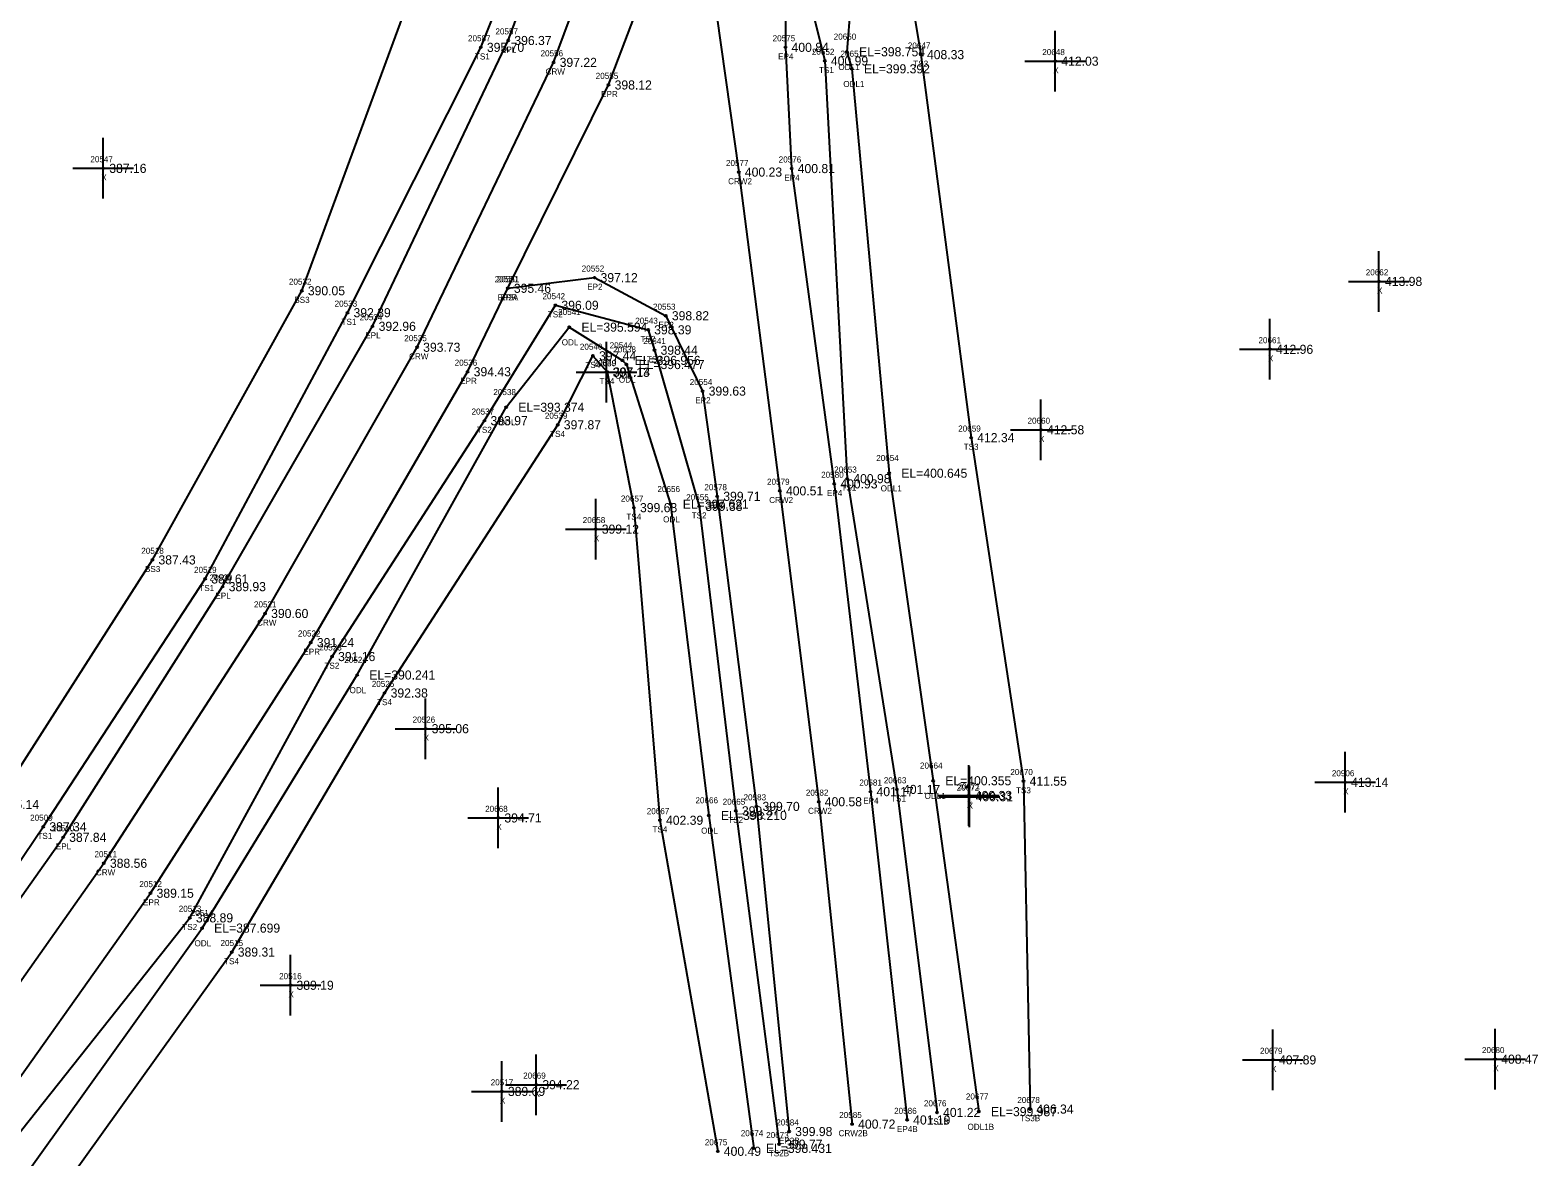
# Model space of a CAD drawing. Extents: x 2116373 to 2118139, y 979529 to 981026.
# Drawn here: x 2117884.9 to 2118133.5, y 980637.9 to 980823.7 of the extents above; entities that cross this region are included whole.
import ezdxf

# ---------------------------------------------------------------- set-up
doc = ezdxf.new("R2010")
doc.units = 0
for name, color, linetype in [('RD_DTM_BkLn1', 7, 'Continuous'), ('RD_DTM_BkLn2', 7, 'Continuous'), ('RD_DTM_BkLn_txCode', 7, 'Continuous'), ('RD_EX_H2O', 7, 'Continuous'), ('RD_EX_H2O_txCode', 7, 'Continuous'), ('RD_EX_Misc', 7, 'Continuous'), ('RD_EX_Misc_txCode', 7, 'Continuous'), ('RD_EX_Road', 7, 'Continuous'), ('RD_EX_Road_txCode', 7, 'Continuous'), ('RD_EX_TX_H2O_ELEV', 7, 'Continuous'), ('RD_EX_TX_Misc_ELEV', 7, 'Continuous'), ('RD_EX_TX_Road_ELEV', 7, 'Continuous'), ('RD_HC_Survey_ELEV', 7, 'Continuous'), ('RD_HC_Survey_txCode', 7, 'Continuous'), ('RD_SMD_Locator', 7, 'Continuous')]:
    doc.layers.add(name, color=color, linetype=linetype)

msp = doc.modelspace()

# ---------------------------------------------------------------- linework, layer by layer
at = {"layer": 'RD_DTM_BkLn1'}
for points in [[(2117394.63, 980185.41), (2117475.35, 980259.39), (2117549.63, 980326.58), (2117623.5, 980394.2), (2117697.55, 980461.75), (2117735.02, 980495.39), (2117805.43, 980566.78), (2117837.53, 980605.36), (2117867.93, 980645.06), (2117897.09, 980686.34), (2117923.66, 980727.51), (2117948.72, 980771.39), (2117971.22, 980818.34), (2117988.96, 980866.05), (2117991.42, 980873.14), (2118004.26, 980915.09), (2118016.82, 980963.49), (2118028.02, 981013.26)], [(2117994.42, 980851.98), (2118001.75, 980800.26), (2118008.52, 980747.72), (2118014.92, 980696.48), (2118020.42, 980643.35)]]:
    msp.add_lwpolyline(points, dxfattribs=at)
at = {"layer": 'RD_DTM_BkLn2'}
for points in [[(2117493.39, 980317.39), (2117496.3, 980311.64), (2117501.39, 980308.35), (2117540.21, 980337.44), (2117614.76, 980403.8), (2117689.51, 980469.61), (2117729.91, 980504.53), (2117761.86, 980538.86), (2117795.32, 980575.41), (2117828.25, 980612.61), (2117859.59, 980651.69), (2117887.1, 980692.35), (2117913.78, 980733.2), (2117937.24, 980777.08), (2117959.23, 980820.82), (2117978.84, 980869.89), (2117994.26, 980920.18), (2118007.51, 980964.57), (2118017.18, 981016.23)], [(2118015.21, 980858.09), (2118013.77, 980827.2), (2118015.93, 980818.58), (2118019.62, 980749.73), (2118027.82, 980698.51), (2118034.42, 980645.27)], [(2118025.45, 980857.32), (2118031.76, 980819.62), (2118040.05, 980756.49), (2118048.68, 980699.87), (2118049.79, 980645.82)], [(2117731.72, 980517.83), (2117742.59, 980526.71), (2117749.81, 980537.43), (2117757.84, 980543.55), (2117791.08, 980578.67), (2117820.63, 980617.19), (2117852.6, 980656.41), (2117879.28, 980696.02), (2117905.09, 980736.34), (2117929.71, 980780.7), (2117946.34, 980825.73), (2117956.18, 980836.51)], [(2117403.18, 980177.15), (2117405.35, 980174.66), (2117487.26, 980245.43), (2117563.99, 980312.17), (2117634.65, 980381.46), (2117704.3, 980451.46), (2117722.65, 980465.11), (2117743.87, 980484.9), (2117780.03, 980521.07), (2117815.83, 980557.8), (2117846.79, 980597.78), (2117878.62, 980636.27), (2117911.26, 980677.34), (2117934.7, 980720.41), (2117959.82, 980759.29), (2117971.51, 980778.31), (2117986.8, 980774.26), (2117987.85, 980770.9), (2117995.22, 980745.17), (2118001.26, 980694.98), (2118008.4, 980640.04)], [(2117734.28, 980458.87), (2117786.65, 980514.59), (2117820.54, 980553.44), (2117855.54, 980590.41), (2117887.71, 980629.08), (2117918.16, 980671.7), (2117943.36, 980714.4), (2117971.9, 980758.61), (2117977.71, 980769.98), (2117980.03, 980767.32), (2117984.46, 980744.95), (2117988.75, 980693.43), (2117998.28, 980638.86)]]:
    msp.add_lwpolyline(points, dxfattribs=at)
at = {"layer": 'RD_EX_H2O'}
for points in [[(2118019.21, 980857.78), (2118020.15, 980827.75), (2118019.57, 980820.09), (2118020.38, 980817.28), (2118026.54, 980750.63), (2118033.78, 980699.94), (2118041.32, 980645.4)], [(2117725.24, 980456.84), (2117729.88, 980462.23), (2117745.69, 980479.89), (2117783.52, 980517.46), (2117819.19, 980554.81), (2117852.43, 980593.07), (2117882.84, 980633.09), (2117913.27, 980675.65), (2117938.84, 980717.37), (2117963.41, 980761.5), (2117973.8, 980774.7), (2117982.58, 980769.22), (2117983.22, 980768.54), (2117990.51, 980745.52), (2117996.79, 980694.22), (2118004.21, 980639.35)]]:
    msp.add_lwpolyline(points, dxfattribs=at)
at = {"layer": 'RD_EX_Misc'}
for p, q in [((2118053.91, 980813.54), (2118053.91, 980823.54)), ((2118048.91, 980818.54), (2118058.91, 980818.54)), ((2117896.98, 980795.88), (2117896.98, 980805.88)), ((2117891.98, 980800.88), (2117901.98, 980800.88)), ((2118107.26, 980777.24), (2118107.26, 980787.24)), ((2118102.26, 980782.24), (2118112.26, 980782.24)), ((2118089.29, 980766.05), (2118089.29, 980776.05)), ((2117979.94, 980762.26), (2117979.94, 980772.26)), ((2118084.29, 980771.05), (2118094.29, 980771.05)), ((2117974.94, 980767.26), (2117984.94, 980767.26)), ((2118051.55, 980752.78), (2118051.55, 980762.78)), ((2118046.55, 980757.78), (2118056.55, 980757.78)), ((2117978.16, 980736.41), (2117978.16, 980746.41)), ((2117973.16, 980741.41), (2117983.16, 980741.41)), ((2117950.12, 980703.52), (2117950.12, 980713.52)), ((2117945.12, 980708.52), (2117955.12, 980708.52)), ((2118039.66, 980692.51), (2118039.66, 980702.51)), ((2118101.68, 980694.68), (2118101.68, 980704.68)), ((2118039.8, 980692.31), (2118039.8, 980702.31)), ((2117962.11, 980688.81), (2117962.11, 980698.81)), ((2118034.66, 980697.51), (2118044.66, 980697.51)), ((2118096.68, 980699.68), (2118106.68, 980699.68)), ((2118034.8, 980697.31), (2118044.8, 980697.31)), ((2117957.11, 980693.81), (2117967.11, 980693.81)), ((2117927.84, 980661.23), (2117927.84, 980671.23)), ((2117922.84, 980666.23), (2117932.84, 980666.23)), ((2118089.79, 980648.93), (2118089.79, 980658.93)), ((2118126.42, 980649.05), (2118126.42, 980659.05)), ((2117962.69, 980643.73), (2117962.69, 980653.73)), ((2117968.37, 980644.84), (2117968.37, 980654.84)), ((2118084.79, 980653.93), (2118094.79, 980653.93)), ((2118121.42, 980654.05), (2118131.42, 980654.05)), ((2117957.69, 980648.73), (2117967.69, 980648.73)), ((2117963.37, 980649.84), (2117973.37, 980649.84))]:
    msp.add_line(p, q, dxfattribs=at)
at = {"layer": 'RD_EX_Road'}
for points in [[(2117394.63, 980185.41), (2117388.45, 980192.75), (2117469.76, 980266.25), (2117487.02, 980282.1), (2117515.02, 980307.24), (2117543.53, 980333.04), (2117617.72, 980400.8), (2117691.88, 980468.07), (2117729.57, 980501.96), (2117798.93, 980572.83), (2117831.02, 980611), (2117861.69, 980650.07), (2117890.37, 980690.61), (2117916.67, 980731.93), (2117941.38, 980774.84), (2117963.75, 980821.95), (2117981.56, 980869.78), (2117996.2, 980917.73), (2118008.9, 980966.42), (2118019.55, 981015.46)], [(2118015.62, 980912.37), (2118010.99, 980870.98), (2118009.51, 980838.78), (2118009.44, 980820.82), (2118010.46, 980800.84), (2118017.48, 980748.87), (2118023.45, 980698.14), (2118029.49, 980644.03)], [(2117394.63, 980185.41), (2117401.85, 980177.36), (2117480.62, 980253.04), (2117556.27, 980319.95), (2117629.74, 980387.35), (2117703.2, 980454.29), (2117741.39, 980488.9), (2117777.53, 980523.58), (2117812.39, 980561.12), (2117844.66, 980599.64), (2117874.87, 980639.35), (2117904.78, 980681.4), (2117931.2, 980722.71), (2117957.05, 980767.35), (2117963.67, 980781.11), (2117980.28, 980814.62), (2117994.42, 980851.98)], [(2117963.67, 980781.11), (2117977.96, 980782.86), (2117989.71, 980776.58), (2117995.78, 980764.16), (2117998.19, 980746.82), (2118004.65, 980695.71), (2118010.04, 980642.12)]]:
    msp.add_lwpolyline(points, dxfattribs=at)
at = {"layer": 'RD_SMD_Locator'}
for centre in [(2117963.75, 980821.95), (2117959.23, 980820.82), (2118009.44, 980820.82), (2118019.57, 980820.09), (2118031.76, 980819.62), (2117971.22, 980818.34), (2118015.93, 980818.58), (2118020.38, 980817.28), (2118053.91, 980818.54), (2117980.28, 980814.62), (2117896.98, 980800.88), (2118001.75, 980800.26), (2118010.46, 980800.84), (2117977.96, 980782.86), (2118107.26, 980782.24), (2117929.71, 980780.7), (2117963.67, 980781.11), (2117963.67, 980781.11), (2117937.24, 980777.08), (2117971.51, 980778.31), (2117941.38, 980774.84), (2117973.8, 980774.7), (2117989.71, 980776.58), (2117986.8, 980774.26), (2117948.72, 980771.39), (2117977.71, 980769.98), (2117987.85, 980770.9), (2118089.29, 980771.05), (2117957.05, 980767.35), (2117979.94, 980767.26), (2117980.03, 980767.32), (2117982.58, 980769.22), (2117983.22, 980768.54), (2117995.78, 980764.16), (2117963.41, 980761.5), (2117959.82, 980759.29), (2117971.9, 980758.61), (2118051.55, 980757.78), (2118040.05, 980756.49), (2118019.62, 980749.73), (2118026.54, 980750.63), (2118008.52, 980747.72), (2118017.48, 980748.87), (2117984.46, 980744.95), (2117990.51, 980745.52), (2117995.22, 980745.17), (2117998.19, 980746.82), (2117978.16, 980741.41), (2117905.09, 980736.34), (2117913.78, 980733.2), (2117916.67, 980731.93), (2117923.66, 980727.51), (2117931.2, 980722.71), (2117934.7, 980720.41), (2117938.84, 980717.37), (2117943.36, 980714.4), (2117950.12, 980708.52), (2118033.78, 980699.94), (2118048.68, 980699.87), (2118023.45, 980698.14), (2118027.82, 980698.51), (2118039.66, 980697.51), (2118039.8, 980697.31), (2118101.68, 980699.68), (2118001.26, 980694.98), (2118004.65, 980695.71), (2118014.92, 980696.48), (2117887.1, 980692.35), (2117962.11, 980693.81), (2117988.75, 980693.43), (2117996.79, 980694.22), (2117890.37, 980690.61), (2117897.09, 980686.34), (2117904.78, 980681.4), (2117911.26, 980677.34), (2117913.27, 980675.65), (2117918.16, 980671.7), (2117927.84, 980666.23), (2118089.79, 980653.93), (2118126.42, 980654.05), (2117962.69, 980648.73), (2117968.37, 980649.84), (2118034.42, 980645.27), (2118041.32, 980645.4), (2118049.79, 980645.82), (2118020.42, 980643.35), (2118029.49, 980644.03), (2118010.04, 980642.12), (2117998.28, 980638.86), (2118004.21, 980639.35), (2118008.4, 980640.04)]:
    msp.add_circle(centre, 0.15, dxfattribs=at)

# ---------------------------------------------------------------- texts
at = {"layer": 'RD_DTM_BkLn_txCode'}
for s, p in [('20587', (2117957.11, 980821.82)), ('TS1', (2117958.26, 980818.82)), ('20652', (2118013.79, 980819.58)), ('20647', (2118029.61, 980820.62)), ('TS1', (2118014.97, 980816.58)), ('TS3', (2118030.51, 980817.62)), ('20532', (2117927.59, 980781.7)), ('BS3', (2117928.48, 980778.7)), ('20542', (2117969.39, 980779.31)), ('20533', (2117935.12, 980778.08)), ('TS2', (2117970.27, 980776.31)), ('TS1', (2117936.27, 980775.08)), ('20543', (2117984.68, 980775.26)), ('20540', (2117975.55, 980770.98)), ('TS2', (2117985.55, 980772.26)), ('20641', (2117985.99, 980771.9)), ('TS2', (2117986.6, 980768.9)), ('TS4', (2117976.47, 980767.98)), ('20640', (2117977.85, 980768.32)), ('TS4', (2117978.79, 980765.32)), ('20537', (2117957.7, 980760.29)), ('20539', (2117969.78, 980759.61)), ('TS2', (2117958.58, 980757.29)), ('TS4', (2117970.65, 980756.61)), ('20659', (2118037.91, 980757.49)), ('TS3', (2118038.81, 980754.49)), ('20653', (2118017.47, 980750.73)), ('20655', (2117993.08, 980746.17)), ('TS1', (2118018.66, 980747.73)), ('20657', (2117982.31, 980745.95)), ('TS4', (2117983.21, 980742.95)), ('TS2', (2117993.98, 980743.17)), ('20518', (2117903.25, 980737.34)), ('BS3', (2117903.86, 980734.34)), ('20519', (2117911.95, 980734.2)), ('TS1', (2117912.82, 980731.2)), ('20523', (2117932.58, 980721.41)), ('TS2', (2117933.45, 980718.41)), ('20525', (2117941.25, 980715.4)), ('TS4', (2117942.12, 980712.4)), ('20663', (2118025.65, 980699.51)), ('20670', (2118046.5, 980700.87)), ('TS1', (2118026.86, 980696.51)), ('TS3', (2118047.44, 980697.87)), ('20667', (2117986.58, 980694.43)), ('20665', (2117999.09, 980695.98)), ('20509', (2117884.94, 980693.35)), ('TS4', (2117987.51, 980691.43)), ('TS2', (2118000.01, 980692.98)), ('TS1', (2117886.14, 980690.35)), ('20513', (2117909.43, 980678.34)), ('TS2', (2117910.02, 980675.34)), ('20515', (2117916.32, 980672.7)), ('TS4', (2117916.91, 980669.7)), ('20678', (2118047.65, 980646.82)), ('20676', (2118032.26, 980646.27)), ('TS1B', (2118032.99, 980643.27)), ('TS3B', (2118048.08, 980643.82)), ('20675', (2117996.14, 980639.86)), ('20673', (2118006.26, 980641.04)), ('TS2B', (2118006.69, 980638.04))]:
    msp.add_text(s, height=1, dxfattribs=at).set_placement(p)
at = {"layer": 'RD_EX_H2O_txCode'}
for s, p in [('20650', (2118017.39, 980822.09)), ('20651', (2118018.52, 980819.28)), ('ODL1', (2118018.16, 980817.09)), ('ODL1', (2118018.97, 980814.28)), ('20541', (2117971.97, 980776.7)), ('ODL', (2117972.56, 980771.7)), ('20544', (2117980.46, 980771.22)), ('20638', (2117981.08, 980770.54)), ('ODL', (2117981.33, 980766.22)), ('20538', (2117961.29, 980763.5)), ('ODL', (2117981.98, 980765.54)), ('ODL', (2117962.17, 980758.5)), ('20654', (2118024.4, 980752.63)), ('20656', (2117988.34, 980747.52)), ('ODL1', (2118025.13, 980747.63)), ('ODL', (2117989.27, 980742.52)), ('20524', (2117936.72, 980719.37)), ('ODL', (2117937.59, 980714.37)), ('20664', (2118031.61, 980701.94)), ('ODL1', (2118032.37, 980696.94)), ('20666', (2117994.6, 980696.22)), ('ODL', (2117995.54, 980691.22)), ('20514', (2117911.43, 980677.65)), ('ODL', (2117912.03, 980672.65)), ('20677', (2118039.18, 980647.4)), ('ODL1B', (2118039.44, 980642.4)), ('20674', (2118002.07, 980641.35))]:
    msp.add_text(s, height=1, dxfattribs=at).set_placement(p)
at = {"layer": 'RD_EX_Misc_txCode'}
for s, p in [('20648', (2118051.77, 980819.54)), ('X', (2118053.59, 980816.54)), ('20547', (2117894.86, 980801.88)), ('X', (2117896.67, 980798.88)), ('20662', (2118105.09, 980783.24)), ('X', (2118106.94, 980780.24)), ('20661', (2118087.4, 980772.05)), ('X', (2118088.97, 980769.05)), ('20639', (2117977.8, 980768.26)), ('X', (2117979.63, 980765.26)), ('20660', (2118049.34, 980758.78)), ('X', (2118051.23, 980755.78)), ('20658', (2117976.02, 980742.41)), ('X', (2117977.85, 980739.41)), ('20526', (2117947.98, 980709.52)), ('X', (2117949.8, 980706.52)), ('20906', (2118099.5, 980700.68)), ('20672', (2118037.66, 980698.31)), ('20671', (2118037.8, 980698.51)), ('X', (2118101.37, 980697.68)), ('20668', (2117959.94, 980694.81)), ('X', (2118039.34, 980695.51)), ('X', (2118039.48, 980695.31)), ('X', (2117961.79, 980691.81)), ('20516', (2117925.98, 980667.23)), ('X', (2117927.52, 980664.23)), ('20679', (2118087.65, 980654.93)), ('20680', (2118124.24, 980655.05)), ('X', (2118089.48, 980651.93)), ('X', (2118126.11, 980652.05)), ('20517', (2117960.85, 980649.73)), ('20669', (2117966.2, 980650.84)), ('X', (2117962.37, 980646.73)), ('X', (2117968.05, 980647.84))]:
    msp.add_text(s, height=1, dxfattribs=at).set_placement(p)
at = {"layer": 'RD_EX_Road_txCode'}
for s, p in [('20557', (2117961.63, 980822.95)), ('20575', (2118007.32, 980821.82)), ('EPL', (2117962.55, 980819.95)), ('EP4', (2118008.23, 980818.82)), ('20555', (2117978.16, 980815.62)), ('EPR', (2117979.05, 980812.62)), ('20576', (2118008.32, 980801.84)), ('EP4', (2118009.26, 980798.84)), ('20552', (2117975.85, 980783.86)), ('20550', (2117961.52, 980782.11)), ('20551', (2117961.84, 980782.11)), ('EP2A', (2117961.98, 980779.11)), ('EPR', (2117962.45, 980779.11)), ('EP2', (2117976.76, 980780.86)), ('20553', (2117987.6, 980777.58)), ('20534', (2117939.26, 980775.84)), ('EP2', (2117988.51, 980774.58)), ('EPL', (2117940.18, 980772.84)), ('20536', (2117954.91, 980768.35)), ('EPR', (2117955.82, 980765.35)), ('20554', (2117993.66, 980765.16)), ('EP2', (2117994.57, 980762.16)), ('20580', (2118015.32, 980749.87)), ('20578', (2117996.07, 980747.82)), ('EP4', (2118016.27, 980746.87)), ('EP2', (2117996.99, 980744.82)), ('20520', (2117914.52, 980732.93)), ('EPL', (2117915.47, 980729.93)), ('20522', (2117929.08, 980723.71)), ('EPR', (2117929.97, 980720.71)), ('20581', (2118021.62, 980699.14)), ('20583', (2118002.53, 980696.71)), ('EP4', (2118022.25, 980696.14)), ('20510', (2117888.5, 980691.61)), ('EP2', (2118003.44, 980693.71)), ('EPL', (2117889.17, 980688.61)), ('20512', (2117902.94, 980682.4)), ('EPR', (2117903.55, 980679.4)), ('20586', (2118027.35, 980645.03)), ('20584', (2118007.92, 980643.12)), ('EP4B', (2118027.81, 980642.03)), ('EP2B', (2118008.36, 980640.12))]:
    msp.add_text(s, height=1, dxfattribs=at).set_placement(p)
at = {"layer": 'RD_EX_TX_H2O_ELEV'}
for s, p in [('EL=398.754', (2118021.57, 980819.34)), ('EL=399.392', (2118022.38, 980816.53)), ('EL=395.594', (2117975.8, 980773.95)), ('EL=396.956', (2117984.58, 980768.47)), ('EL=396.477', (2117985.22, 980767.79)), ('EL=393.374', (2117965.41, 980760.75)), ('EL=400.645', (2118028.54, 980749.88)), ('EL=397.621', (2117992.51, 980744.77)), ('EL=390.241', (2117940.84, 980716.62)), ('EL=400.355', (2118035.78, 980699.19)), ('EL=398.210', (2117998.79, 980693.47)), ('EL=387.699', (2117915.27, 980674.9)), ('EL=399.987', (2118043.32, 980644.65)), ('EL=398.431', (2118006.21, 980638.6))]:
    msp.add_text(s, height=1.5, dxfattribs=at).set_placement(p)
at = {"layer": 'RD_EX_TX_Misc_ELEV'}
for s, p in [('395.70', (2117960.23, 980820.07)), ('400.99', (2118016.93, 980817.83)), ('408.33', (2118032.76, 980818.87)), ('412.03', (2118054.91, 980817.79)), ('387.16', (2117897.98, 980800.13)), ('413.98', (2118108.26, 980781.49)), ('390.05', (2117930.71, 980779.95)), ('392.39', (2117938.24, 980776.33)), ('396.09', (2117972.51, 980777.56)), ('398.39', (2117987.8, 980773.51)), ('397.44', (2117978.71, 980769.23)), ('398.44', (2117988.85, 980770.15)), ('412.96', (2118090.29, 980770.3)), ('397.13', (2117980.94, 980766.51)), ('397.14', (2117981.03, 980766.57)), ('393.97', (2117960.82, 980758.54)), ('397.87', (2117972.9, 980757.86)), ('412.34', (2118041.05, 980755.74)), ('412.58', (2118052.55, 980757.03)), ('400.98', (2118020.62, 980748.98)), ('399.68', (2117985.46, 980744.2)), ('399.38', (2117996.22, 980744.42)), ('399.12', (2117979.16, 980740.66)), ('387.43', (2117906.09, 980735.59)), ('389.61', (2117914.78, 980732.45)), ('391.16', (2117935.7, 980719.66)), ('392.38', (2117944.36, 980713.65)), ('395.06', (2117951.12, 980707.77)), ('411.55', (2118049.68, 980699.12)), ('413.14', (2118102.68, 980698.93)), ('401.17', (2118028.82, 980697.76)), ('400.33', (2118040.66, 980696.76)), ('400.31', (2118040.8, 980696.56)), ('385.14', (2117880.28, 980695.27)), ('399.37', (2118002.26, 980694.23)), ('387.34', (2117888.1, 980691.6)), ('394.71', (2117963.11, 980693.06)), ('402.39', (2117989.75, 980692.68)), ('388.89', (2117912.26, 980676.59)), ('389.31', (2117919.16, 980670.95)), ('389.19', (2117928.84, 980665.48)), ('407.89', (2118090.79, 980653.18)), ('408.47', (2118127.42, 980653.3)), ('394.22', (2117969.37, 980649.09)), ('389.69', (2117963.69, 980647.98)), ('401.22', (2118035.42, 980644.52)), ('406.34', (2118050.79, 980645.07)), ('399.77', (2118009.4, 980639.29)), ('400.49', (2117999.28, 980638.11))]:
    msp.add_text(s, height=1.5, dxfattribs=at).set_placement(p)
at = {"layer": 'RD_EX_TX_Road_ELEV'}
for s, p in [('396.37', (2117964.75, 980821.2)), ('400.84', (2118010.44, 980820.07)), ('398.12', (2117981.28, 980813.87)), ('400.81', (2118011.46, 980800.09)), ('397.12', (2117978.96, 980782.11)), ('395.46', (2117964.67, 980780.36)), ('395.46', (2117964.67, 980780.36)), ('398.82', (2117990.71, 980775.83)), ('392.96', (2117942.38, 980774.09)), ('394.43', (2117958.05, 980766.6)), ('399.63', (2117996.78, 980763.41)), ('400.93', (2118018.48, 980748.12)), ('399.71', (2117999.19, 980746.07)), ('389.93', (2117917.67, 980731.18)), ('391.24', (2117932.2, 980721.96)), ('401.17', (2118024.45, 980697.39)), ('399.70', (2118005.65, 980694.96)), ('387.84', (2117891.37, 980689.86)), ('389.15', (2117905.78, 980680.65)), ('399.98', (2118011.04, 980641.37)), ('401.19', (2118030.49, 980643.28))]:
    msp.add_text(s, height=1.5, dxfattribs=at).set_placement(p)
at = {"layer": 'RD_HC_Survey_ELEV'}
for s, p in [('397.22', (2117972.22, 980817.59)), ('400.23', (2118002.75, 980799.51)), ('393.73', (2117949.72, 980770.64)), ('400.51', (2118009.52, 980746.97)), ('390.60', (2117924.66, 980726.76)), ('400.58', (2118015.92, 980695.73)), ('388.56', (2117898.09, 980685.59)), ('400.72', (2118021.42, 980642.6))]:
    msp.add_text(s, height=1.5, dxfattribs=at).set_placement(p)
at = {"layer": 'RD_HC_Survey_txCode'}
for s, p in [('20556', (2117969.07, 980819.34)), ('CRW', (2117969.9, 980816.34)), ('20577', (2117999.63, 980801.26)), ('CRW2', (2117999.99, 980798.26)), ('20535', (2117946.6, 980772.39)), ('CRW', (2117947.4, 980769.39)), ('20579', (2118006.4, 980748.72)), ('CRW2', (2118006.76, 980745.72)), ('20521', (2117921.83, 980728.51)), ('CRW', (2117922.35, 980725.51)), ('20582', (2118012.8, 980697.48)), ('CRW2', (2118013.16, 980694.48)), ('20511', (2117895.54, 980687.34)), ('CRW', (2117895.78, 980684.34)), ('20585', (2118018.3, 980644.35)), ('CRW2B', (2118018.19, 980641.35))]:
    msp.add_text(s, height=1, dxfattribs=at).set_placement(p)

doc.saveas('drawing.dxf')
